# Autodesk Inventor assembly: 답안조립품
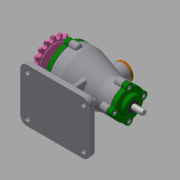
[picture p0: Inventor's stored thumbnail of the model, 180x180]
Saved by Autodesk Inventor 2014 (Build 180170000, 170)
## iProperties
Created: 2020-12
Part Number: 답안조립품
Document SubType Name: Assembly
Designer: kh
Author: kh
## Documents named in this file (15)
- C:\Users\kh\Desktop\701206V1031\답안조립품.iam
- C:\Users\kh\Desktop\701206V1031\개스킷 A.ipt
- C:\Users\kh\Desktop\701206V1031\개스킷 B.ipt
- C:\Users\kh\Desktop\701206V1031\뒤커버.ipt
- C:\Users\kh\Desktop\701206V1031\마개.ipt
- C:\Users\kh\Desktop\701206V1031\베어링 6200.ipt
- C:\Users\kh\Desktop\701206V1031\베어링 6203.ipt
- C:\Users\kh\Desktop\701206V1031\본체.ipt
- C:\Users\kh\Desktop\701206V1031\볼트 M5.ipt
- C:\Users\kh\Desktop\701206V1031\스프로킷.ipt
- C:\Users\kh\Desktop\701206V1031\앞커버.ipt
- C:\Users\kh\Desktop\701206V1031\오일 실 10 20 7.ipt
- C:\Users\kh\Desktop\701206V1031\오일 실 17 30 8.ipt
- C:\Users\kh\Desktop\701206V1031\축.ipt
- C:\Users\kh\Desktop\701206V1031\키 4x4x14.ipt
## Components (2 placed, 2 different names)
1. 개스킷 A:1 — Mate:9, Mate:10, Mate:11, Mate:17
2. 개스킷 B:1 — Mate:12, Mate:13, Mate:14, Mate:15
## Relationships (8: Mate 8)
- Mate:9: 개스킷 A:1
- Mate:10: 개스킷 A:1
- Mate:11: 개스킷 A:1
- Mate:12: 개스킷 B:1
- Mate:13: 개스킷 B:1
- Mate:14: 개스킷 B:1
- Mate:15: 개스킷 B:1
- Mate:17: 개스킷 A:1
